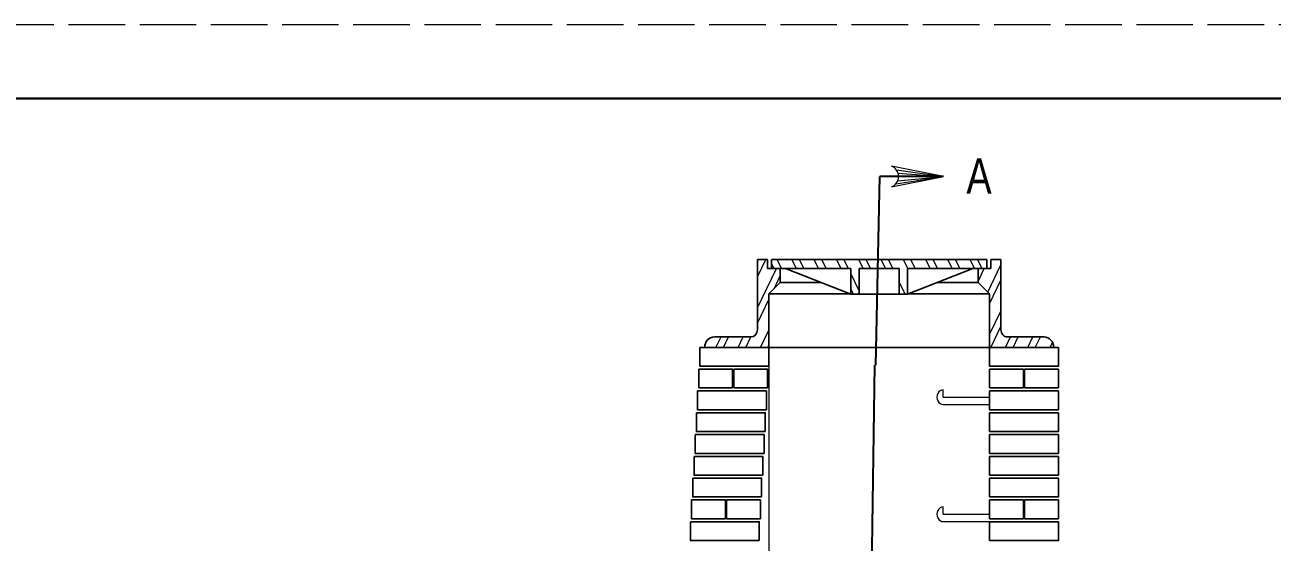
# Model space of a CAD drawing. Extents: x 750.7 to 784.7, y 860.1 to 882.1.
# Drawn here: x 758.32 to 766.8, y 878.6 to 882.12 of the extents above; entities that cross this region are included whole.
import ezdxf

# ---------------------------------------------------------------- set-up
doc = ezdxf.new("R2010")
doc.units = 0
doc.header["$LTSCALE"] = 0.064
doc.linetypes.add('LONG_DASHED', pattern=[7.5, 6, -1.5])
doc.layers.add('1', color=7, linetype='Continuous', lineweight=13)

msp = doc.modelspace()

# ---------------------------------------------------------------- linework, layer by layer
at = {"layer": '1', "lineweight": 25}
for p, q in [((752.65083, 881.61842), (784.15083, 881.61842)), ((763.29842, 880.0445), (763.29842, 880.522)), ((763.29842, 880.522), (763.36592, 880.522)), ((763.36592, 880.46075), (763.36592, 880.522)), ((763.39433, 880.46075), (763.39433, 880.522)), ((763.39433, 880.522), (764.85758, 880.522)), ((764.85758, 880.46067), (764.85758, 880.522)), ((764.886, 880.46067), (764.886, 880.522)), ((764.95342, 880.522), (764.886, 880.522)), ((764.95342, 880.0445), (764.95342, 880.522)), ((763.36592, 880.46075), (763.93233, 880.46075)), ((763.45392, 880.36667), (763.45392, 880.46075)), ((763.93233, 880.2865), (763.48958, 880.46075)), ((763.93233, 880.2865), (763.93233, 880.46075)), ((763.98917, 880.28617), (763.98917, 880.46075)), ((763.98917, 880.46075), (764.26275, 880.46075)), ((764.26275, 880.28617), (764.26275, 880.46075)), ((764.3195, 880.2865), (764.3195, 880.46075)), ((764.3195, 880.46075), (764.886, 880.46067)), ((764.3195, 880.2865), (764.76225, 880.46067)), ((764.79792, 880.36667), (764.79792, 880.46067)), ((763.37542, 880.2885), (763.45392, 880.36667)), ((763.45392, 880.36667), (763.72867, 880.36667)), ((764.52325, 880.36667), (764.79792, 880.36667)), ((764.8765, 880.28842), (764.79792, 880.36667)), ((763.37542, 879.92525), (763.37542, 880.2885)), ((763.37542, 880.2885), (763.92742, 880.2885)), ((763.93233, 880.2865), (763.98917, 880.28617)), ((764.26275, 880.28617), (763.98917, 880.28617)), ((764.3195, 880.2865), (764.26275, 880.28617)), ((764.32442, 880.2885), (764.8765, 880.28842)), ((763.00542, 879.99625), (763.25367, 879.99625)), ((765.24642, 879.99617), (764.99817, 879.99625)), ((762.93967, 879.92533), (764.8765, 879.92525)), ((762.89958, 879.649), (762.89958, 879.777)), ((763.13717, 879.649), (763.13717, 879.777)), ((764.8765, 879.649), (764.8765, 879.777)), ((765.114, 879.649), (765.114, 879.777)), ((763.12975, 879.649), (762.89958, 879.649)), ((763.36733, 879.649), (763.13717, 879.649)), ((765.10658, 879.649), (764.8765, 879.649)), ((765.34417, 879.649), (765.114, 879.649)), ((762.851, 878.75933), (762.851, 878.88742)), ((763.0885, 878.75933), (763.0885, 878.88742)), ((764.8765, 878.75933), (764.8765, 878.88742)), ((765.114, 878.75933), (765.114, 878.88742)), ((763.08108, 878.75933), (762.851, 878.75933)), ((763.31867, 878.75933), (763.0885, 878.75933)), ((765.10658, 878.75933), (764.8765, 878.75933)), ((765.34417, 878.75933), (765.114, 878.75933))]:
    msp.add_line(p, q, dxfattribs=at)
at = {"layer": '1', "lineweight": 35}
for p, q in [((764.1035, 879.80375), (764.13058, 881.08717)), ((764.56358, 881.08717), (764.13058, 881.08717)), ((764.06808, 877.90742), (764.09633, 879.80392))]:
    msp.add_line(p, q, dxfattribs=at)
at = {"layer": '1'}
for p, q in [((764.23917, 881.03758), (764.56358, 881.08717)), ((764.243, 881.13208), (764.56358, 881.08717)), ((764.2515, 881.05842), (764.56358, 881.08717)), ((764.25383, 881.10983), (764.56358, 881.08717)), ((764.25717, 881.08717), (764.56358, 881.08717)), ((763.29842, 880.40408), (763.3555, 880.522)), ((763.29842, 880.5085), (763.305, 880.522)), ((763.4115, 880.46075), (763.39433, 880.49625)), ((763.46192, 880.46075), (763.43233, 880.522)), ((763.47342, 880.522), (763.80375, 880.522)), ((763.56292, 880.46075), (763.53325, 880.522)), ((763.61342, 880.46075), (763.58375, 880.522)), ((763.71442, 880.46075), (763.68475, 880.522)), ((763.76483, 880.46075), (763.73525, 880.522)), ((763.83617, 880.522), (763.86583, 880.46075)), ((763.91633, 880.46075), (763.88667, 880.522)), ((764.01733, 880.46075), (763.98767, 880.522)), ((764.06775, 880.46075), (764.03817, 880.522)), ((764.16875, 880.46075), (764.13908, 880.522)), ((764.21925, 880.46075), (764.18958, 880.522)), ((764.32025, 880.46075), (764.29058, 880.522)), ((764.37067, 880.46075), (764.34108, 880.522)), ((764.47167, 880.46075), (764.442, 880.522)), ((764.52217, 880.46067), (764.4925, 880.522)), ((764.62308, 880.46067), (764.5935, 880.522)), ((764.67358, 880.46067), (764.644, 880.522)), ((764.77458, 880.46067), (764.74492, 880.522)), ((764.82508, 880.46067), (764.79542, 880.522)), ((764.86408, 880.30083), (764.95342, 880.48558)), ((763.29842, 880.19533), (763.42683, 880.46075)), ((763.41125, 880.32417), (763.45392, 880.41242)), ((763.98917, 880.31017), (763.93233, 880.42758)), ((764.79792, 880.37292), (764.84042, 880.46067)), ((763.93233, 880.32325), (763.95017, 880.28642)), ((764.3035, 880.28642), (764.26275, 880.37075)), ((764.8765, 880.22217), (764.95342, 880.38125)), ((763.29842, 880.09092), (763.37542, 880.25008)), ((764.8765, 880.01333), (764.95342, 880.17242)), ((764.88433, 879.92525), (764.95342, 880.06808)), ((763.01642, 879.92533), (763.05075, 879.99625)), ((763.06692, 879.92533), (763.10117, 879.99625)), ((763.16783, 879.92525), (763.20217, 879.99625)), ((763.21833, 879.92525), (763.25267, 879.99625)), ((763.31933, 879.92525), (763.37542, 880.04125)), ((764.98533, 879.92525), (765.01967, 879.99625)), ((765.03583, 879.92525), (765.07017, 879.99625)), ((765.13683, 879.92525), (765.17108, 879.99617)), ((765.18725, 879.92525), (765.22158, 879.99617)), ((763.36983, 879.92525), (763.37542, 879.93683)), ((763.37542, 879.93708), (763.37542, 877.47533)), ((765.28825, 879.92525), (765.30442, 879.95875)), ((764.56192, 879.58658), (764.56192, 879.63667)), ((764.56192, 879.58658), (764.87642, 879.58658)), ((764.56192, 879.5365), (764.87642, 879.5365)), ((764.56192, 878.79), (764.56192, 878.84008)), ((764.56192, 878.79), (764.87642, 878.79)), ((764.56192, 878.73992), (764.87642, 878.73992))]:
    msp.add_line(p, q, dxfattribs=at)
at = {"layer": '1', "linetype": 'LONG_DASHED'}
msp.add_lwpolyline([(750.65083, 860.11842), (784.65083, 860.11842), (784.65083, 882.11842), (750.65083, 882.11842)], close=True, dxfattribs=at)
at = {"layer": '1', "lineweight": 40}
msp.add_lwpolyline([(752.65083, 881.61842), (784.15083, 881.61842), (784.15083, 860.61842), (752.65083, 860.61842)], close=True, dxfattribs=at)
at = {"layer": '1'}
msp.add_lwpolyline([(764.20942, 881.01633), (764.56358, 881.08717), (764.20942, 881.158)], dxfattribs=at)
at = {"layer": '1', "lineweight": 25}
for points in [[(765.31225, 879.92525), (764.8765, 879.92525), (764.8765, 880.28842)], [(763.37542, 879.79725), (763.37542, 879.92525), (762.90775, 879.92525)], [(763.37542, 879.79725), (762.90775, 879.79725), (762.90775, 879.92525)], [(764.8765, 879.79725), (764.8765, 879.92525), (765.34417, 879.92525)], [(764.8765, 879.79725), (765.34417, 879.79725), (765.34417, 879.92525)], [(763.12975, 879.649), (763.12975, 879.777), (762.89958, 879.777)], [(763.36733, 879.649), (763.36733, 879.777), (763.13717, 879.777)], [(765.10658, 879.649), (765.10658, 879.777), (764.8765, 879.777)], [(765.34417, 879.649), (765.34417, 879.777), (765.114, 879.777)], [(763.35917, 879.50067), (763.35917, 879.62875), (762.8915, 879.62875)], [(763.35917, 879.50067), (762.8915, 879.50067), (762.8915, 879.62875)], [(764.8765, 879.50067), (764.8765, 879.62875), (765.34417, 879.62875)], [(764.8765, 879.50067), (765.34417, 879.50067), (765.34417, 879.62875)], [(763.35108, 879.35242), (763.35108, 879.4805), (762.88342, 879.4805)], [(763.35108, 879.35242), (762.88342, 879.35242), (762.88342, 879.4805)], [(764.8765, 879.35242), (764.8765, 879.4805), (765.34417, 879.4805)], [(764.8765, 879.35242), (765.34417, 879.35242), (765.34417, 879.4805)], [(763.343, 879.20417), (763.343, 879.33225), (762.87533, 879.33225)], [(763.343, 879.20417), (762.87533, 879.20417), (762.87533, 879.33225)], [(764.8765, 879.20417), (764.8765, 879.33225), (765.34417, 879.33225)], [(764.8765, 879.20417), (765.34417, 879.20417), (765.34417, 879.33225)], [(763.33483, 879.05592), (763.33492, 879.184), (762.86717, 879.184)], [(763.33483, 879.05592), (762.86717, 879.05592), (762.86717, 879.184)], [(764.8765, 879.05592), (764.8765, 879.184), (765.34417, 879.184)], [(764.8765, 879.05592), (765.34417, 879.05592), (765.34417, 879.184)], [(763.32675, 878.90767), (763.32675, 879.03567), (762.85908, 879.03567)], [(763.32675, 878.90767), (762.85908, 878.90767), (762.85908, 879.03567)], [(764.8765, 878.90767), (764.8765, 879.03567), (765.34417, 879.03567)], [(764.8765, 878.90767), (765.34417, 878.90767), (765.34417, 879.03567)], [(763.08108, 878.75933), (763.08108, 878.88742), (762.851, 878.88742)], [(763.31867, 878.75933), (763.31867, 878.88742), (763.0885, 878.88742)], [(765.10658, 878.75933), (765.10658, 878.88742), (764.8765, 878.88742)], [(765.34417, 878.75933), (765.34417, 878.88742), (765.114, 878.88742)], [(763.31058, 878.61108), (763.31058, 878.73917), (762.84292, 878.73917)], [(763.31058, 878.61108), (762.84292, 878.61108), (762.84292, 878.73917)], [(764.8765, 878.61108), (764.8765, 878.73917), (765.34417, 878.73917)], [(764.8765, 878.61108), (765.34417, 878.61108), (765.34417, 878.73917)]]:
    msp.add_lwpolyline(points, dxfattribs=at)
at = {"layer": '1'}
msp.add_arc((764.18084, 881.08724), 0.07644, 292.08605, 67.91218, dxfattribs=at)
at = {"layer": '1', "lineweight": 25}
for centre, major_axis, start_param, end_param in [((763.00543, 879.9253), (0.00002, -0.07096), 3.1413023, 4.7120987), ((763.25369, 880.04454), (-0.00001, 0.04829), 3.1412986, 4.7120928), ((764.99819, 880.0445), (0.00001, -0.04829), 4.7120939, 6.2828923), ((765.24646, 879.92524), (0.00002, -0.07096), 1.5704964, 3.1412927)]:
    msp.add_ellipse(centre, major_axis=major_axis, ratio=0.926969, start_param=start_param, end_param=end_param, dxfattribs=at)
at = {"layer": '1'}
for centre in [(764.56192, 879.58659), (764.56192, 878.79)]:
    msp.add_ellipse(centre, major_axis=(0, 0.05012), ratio=0.869565, start_param=0.000003, end_param=3.1415958, dxfattribs=at)

# ---------------------------------------------------------------- texts
at = {"layer": '1', "width": 0.8}
msp.add_text('A', height=0.24, dxfattribs=at).set_placement((764.71908, 880.97133))

doc.saveas('drawing.dxf')
